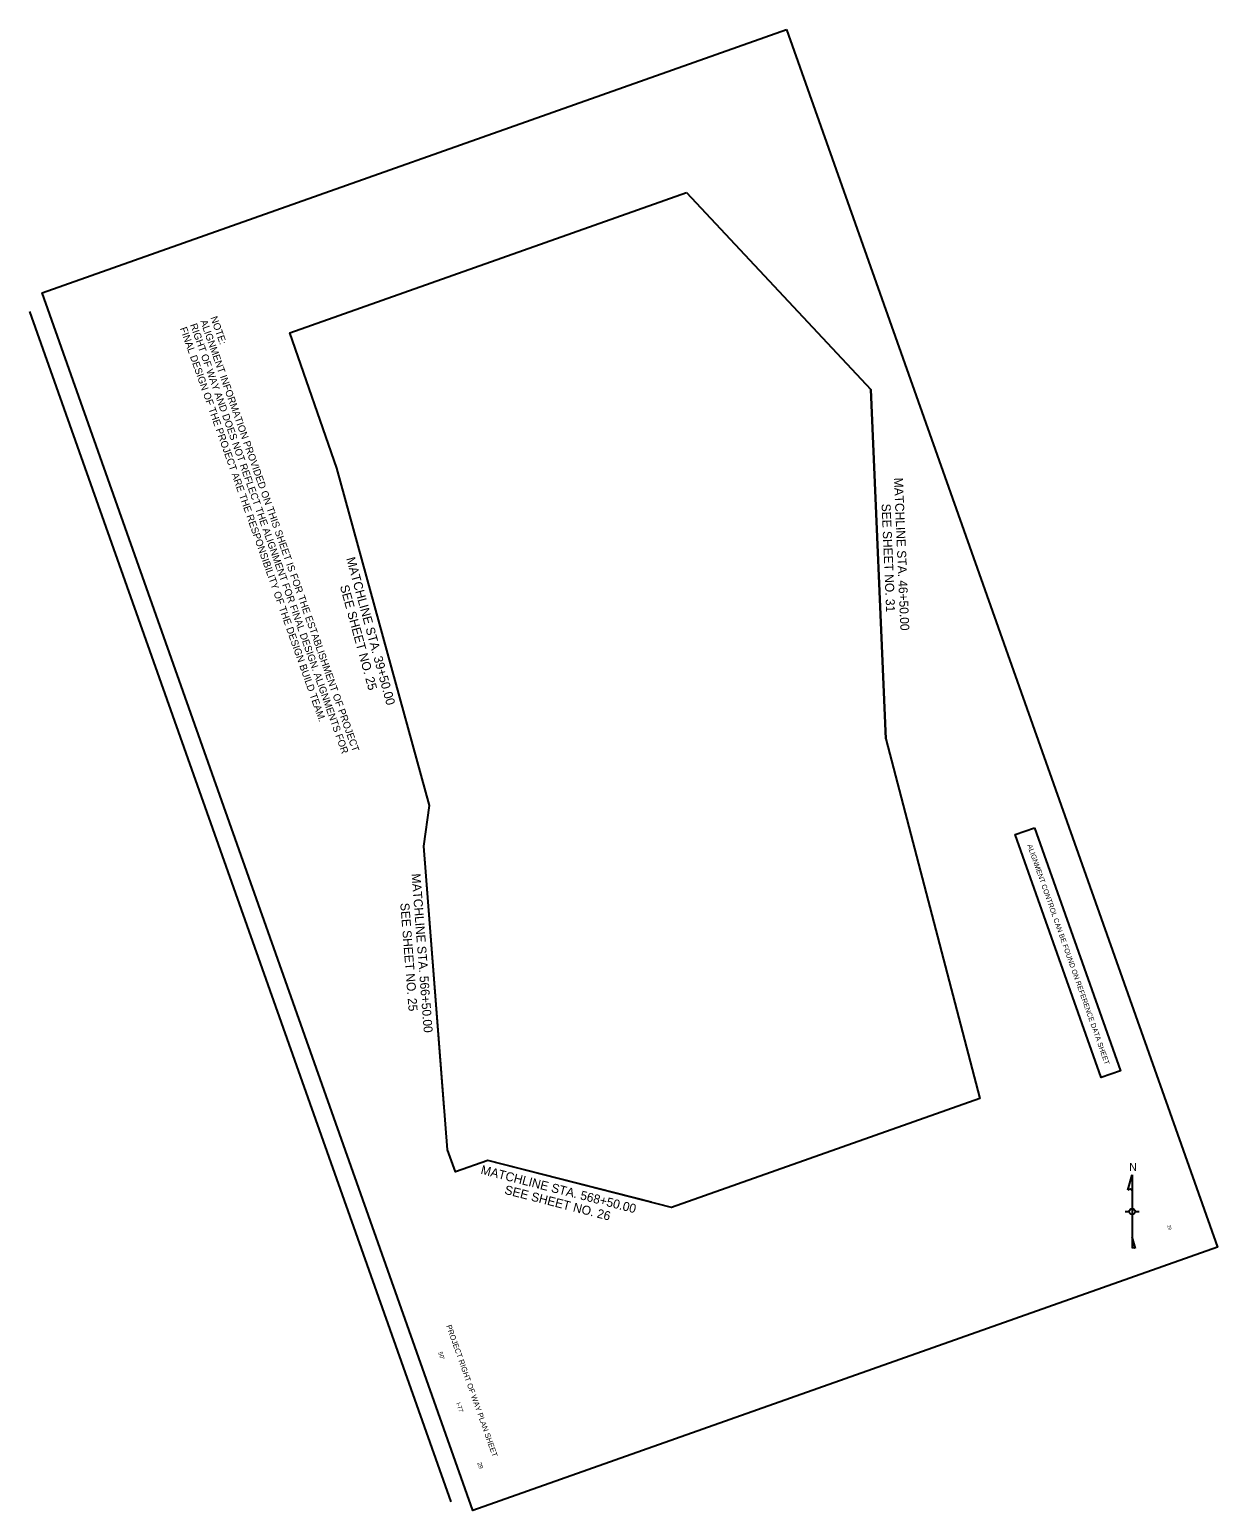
# Model space of a CAD drawing. Extents: x 2005793 to 2007447, y 1135965 to 1138029.
import ezdxf

# ---------------------------------------------------------------- set-up
doc = ezdxf.new("R2010")
doc.units = 0
for name, color, linetype in [('North Arrow', 7, 'Continuous'), ('RD_SHT_IplotShp', 7, 'Continuous'), ('RD_SHT_MatchLine', 7, 'Continuous'), ('RD_SHT_Misc1', 7, 'Continuous'), ('RD_SHT_ShtClip', 7, 'Continuous'), ('RD_SHT_TX', 7, 'Continuous')]:
    doc.layers.add(name, color=color, linetype=linetype)

msp = doc.modelspace()

# ---------------------------------------------------------------- linework, layer by layer
at = {"layer": 'North Arrow'}
for p, q in [((2007322.7, 1136411.5), (2007328.6, 1136432.5)), ((2007328.6, 1136432.5), (2007328.6, 1136410.3)), ((2007328.6, 1136432.5), (2007328.6, 1136330.3)), ((2007318.9, 1136381.4), (2007324.6, 1136381.4)), ((2007332.6, 1136381.4), (2007338.3, 1136381.4)), ((2007328.6, 1136346.1), (2007328.6, 1136330.3)), ((2007333.2, 1136330), (2007328.6, 1136346.1))]:
    msp.add_line(p, q, dxfattribs=at)
msp.add_circle((2007328.6, 1136381.4), 4.02, dxfattribs=at)
for centre, radius, start, end in [((2007325.3, 1136409), 3.59, 22.3707, 136.1387), ((2007330.8, 1136327.8), 3.3, 43.3397, 130.5607)]:
    msp.add_arc(centre, radius, start, end, dxfattribs=at)
at = {"layer": 'RD_SHT_IplotShp'}
msp.add_lwpolyline([(2006847, 1138028.8), (2007447.3, 1136331.8), (2006410.3, 1135965), (2005810, 1137661.9)], close=True, dxfattribs=at)
at = {"layer": 'RD_SHT_MatchLine'}
for p, q in [((2006985.3, 1137040.4), (2006964.4, 1137527.4)), ((2006349.9, 1136947.4), (2006220.5, 1137417.4)), ((2006370.2, 1136526.2), (2006341.8, 1136890.8)), ((2006659.1, 1136394.4), (2006431, 1136452.8))]:
    msp.add_line(p, q, dxfattribs=at)
at = {"layer": 'RD_SHT_ShtClip'}
msp.add_lwpolyline([(2006707.7, 1137801.6), (2006964.4, 1137527.4), (2006985.3, 1137040.4), (2007116.6, 1136539.2), (2006687, 1136387.3), (2006431, 1136452.8), (2006385.9, 1136436.9), (2006374.8, 1136467.3), (2006341.8, 1136890.8), (2006349.9, 1136947.4), (2006220.5, 1137417.4), (2006155.1, 1137606.1)], close=True, dxfattribs=at)
at = {"layer": 'RD_SHT_TX'}
msp.add_line((2005792.6, 1137636), (2006379.6, 1135976.8), dxfattribs=at)
msp.add_lwpolyline([(2007192.5, 1136916.4), (2007312.3, 1136577.8), (2007285.5, 1136568.4), (2007165.7, 1136906.9)], close=True, dxfattribs=at)

# ---------------------------------------------------------------- texts
at = {"layer": 'North Arrow'}
msp.add_text('N', height=11.1, dxfattribs=at).set_placement((2007324.5, 1136438))
at = {"layer": 'RD_SHT_MatchLine'}
for s, rotation, p in [('MATCHLINE STA. 46+50.00', 272.4547, (2006996.7, 1137404)), ('SEE SHEET NO. 31', 272.4547, (2006979.5, 1137367.8)), ('MATCHLINE STA. 39+50.00', 285.3889, (2006233.6, 1137291.7)), ('SEE SHEET NO. 25', 285.3889, (2006224.8, 1137252.9)), ('MATCHLINE STA. 566+50.00', 274.4504, (2006324.6, 1136852.1)), ('SEE SHEET NO. 25', 274.4504, (2006309, 1136811.1)), ('MATCHLINE STA. 568+50.00', 345.6281, (2006420.2, 1136434.2)), ('SEE SHEET NO. 26', 345.6281, (2006453.4, 1136406.3))]:
    msp.add_text(s, height=12.5, rotation=rotation, dxfattribs=at).set_placement(p)
at = {"layer": 'RD_SHT_Misc1'}
for s, p in [('FINAL DESIGN OF THE PROJECT ARE THE RESPONSIBILITY OF THE DESIGN BUILD TEAM.', (2006001.9, 1137612.3)), ('RIGHT OF WAY AND DOES NOT REFLECT THE ALIGNMENT FOR FINAL DESIGN. ALIGNMENTS FOR', (2006016, 1137617.3)), ('ALIGNMENT INFORMATION PROVIDED ON THIS SHEET IS FOR THE ESTABLISHMENT OF PROJECT', (2006030.2, 1137622.3)), ('NOTE:', (2006044.3, 1137627.3))]:
    msp.add_text(s, height=10, rotation=289.482, dxfattribs=at).set_placement(p)
at = {"layer": 'RD_SHT_TX'}
for s, height, p in [('ALIGNMENT CONTROL CAN BE FOUND ON REFERENCE DATA SHEET', 7, (2007182.4, 1136891.8)), ('29', 4.5, (2007377.3, 1136361.9)), ('PROJECT RIGHT OF WAY PLAN SHEET', 7.5, (2006372.9, 1136222.1)), ("50'", 6, (2006361.7, 1136184.9)), ('I-77', 6, (2006386.7, 1136114.3)), ('29', 6, (2006416.1, 1136031))]:
    msp.add_text(s, height=height, rotation=289.482, dxfattribs=at).set_placement(p)

doc.saveas('drawing.dxf')
